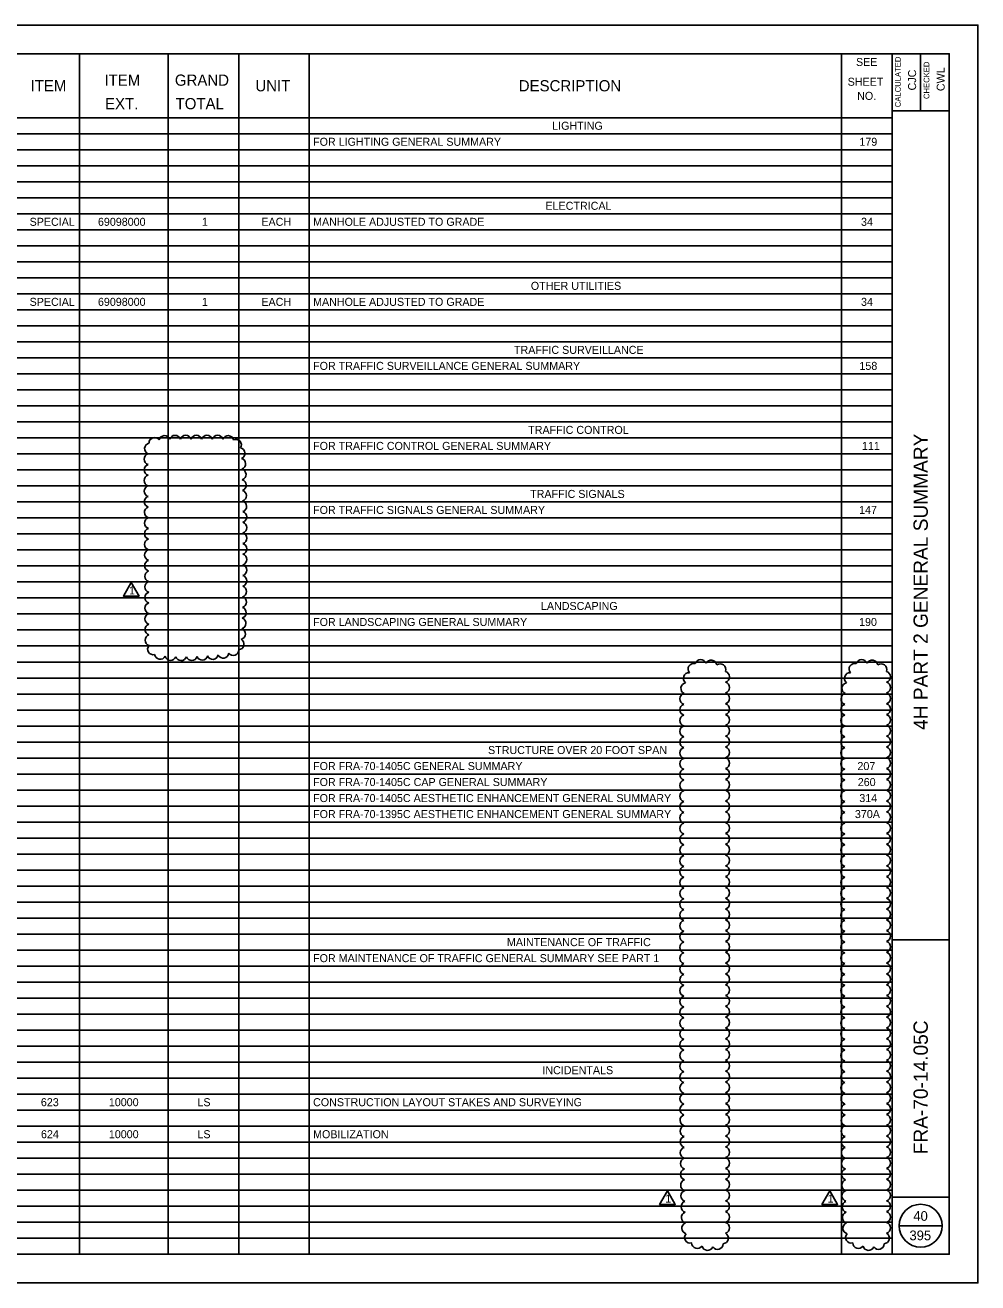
# Model space of a CAD drawing. Extents: x 0 to 34, y 0 to 22.
# Drawn here: x 17.34 to 34, y 0 to 22 of the extents above; entities that cross this region are included whole.
import ezdxf

# ---------------------------------------------------------------- set-up
doc = ezdxf.new("R2010")
doc.units = 0
for name, color, linetype in [('SH_Border', 7, 'Continuous'), ('SH_Cut_Line', 7, 'Continuous'), ('SH_Data', 7, 'Continuous'), ('SH_Text', 7, 'Continuous'), ('TX_P_1000', 7, 'Continuous')]:
    doc.layers.add(name, color=color, linetype=linetype)

msp = doc.modelspace()

# ---------------------------------------------------------------- linework, layer by layer
at = {"layer": 'SH_Border'}
for p, q in [((32.5, 0.5), (32.5, 21.5)), ((33, 21.5), (33, 20.5)), ((32.5, 20.5), (33.5, 20.5)), ((32.5, 6), (33.5, 6)), ((32.5, 1.5), (33.5, 1.5))]:
    msp.add_line(p, q, dxfattribs=at)
msp.add_lwpolyline([(2, 21.5), (33.5, 21.5), (33.5, 0.5), (2, 0.5)], close=True, dxfattribs=at)
at = {"layer": 'SH_Cut_Line'}
msp.add_lwpolyline([(0, 0), (34, 0), (34, 22), (0, 22)], close=True, dxfattribs=at)
at = {"layer": 'SH_Data'}
for p, q in [((17.252, 21.5), (32.504, 21.5)), ((18.289, 21.5), (18.289, 0.5)), ((19.838, 21.5), (19.838, 0.5)), ((21.073, 21.5), (21.073, 0.5)), ((22.308, 21.5), (22.308, 0.5)), ((31.614, 21.5), (31.614, 0.5)), ((32.504, 21.5), (32.504, 0.5)), ((2, 20.38), (32.504, 20.38)), ((2, 20.1), (32.504, 20.1)), ((2, 19.82), (32.504, 19.82)), ((2, 19.54), (32.504, 19.54)), ((2, 19.26), (32.504, 19.26)), ((2, 18.98), (32.504, 18.98)), ((2, 18.7), (32.504, 18.7)), ((2, 18.42), (32.504, 18.42)), ((2, 18.14), (32.504, 18.14)), ((2, 17.86), (32.504, 17.86)), ((2, 17.58), (32.504, 17.58)), ((2, 17.3), (32.504, 17.3)), ((2, 17.02), (32.504, 17.02)), ((2, 16.74), (32.504, 16.74)), ((2, 16.46), (32.504, 16.46)), ((2, 16.18), (32.504, 16.18)), ((2, 15.9), (32.504, 15.9)), ((2, 15.62), (32.504, 15.62)), ((2, 15.34), (32.504, 15.34)), ((2, 15.06), (32.504, 15.06)), ((2, 14.78), (32.504, 14.78)), ((2, 14.5), (32.504, 14.5)), ((2, 14.22), (32.504, 14.22)), ((2, 13.94), (32.504, 13.94)), ((2, 13.66), (32.504, 13.66)), ((2, 13.38), (32.504, 13.38)), ((2, 13.1), (32.504, 13.1)), ((2, 12.82), (32.504, 12.82)), ((2, 12.54), (32.504, 12.54)), ((2, 12.26), (32.504, 12.26)), ((2, 11.98), (32.504, 11.98)), ((2, 11.7), (32.504, 11.7)), ((2, 11.42), (32.504, 11.42)), ((2, 11.14), (32.504, 11.14)), ((2, 10.86), (32.504, 10.86)), ((2, 10.58), (32.504, 10.58)), ((2, 10.3), (32.504, 10.3)), ((2, 10.02), (32.504, 10.02)), ((2, 9.74), (32.504, 9.74)), ((2, 9.46), (32.504, 9.46)), ((2, 9.18), (32.504, 9.18)), ((2, 8.9), (32.504, 8.9)), ((2, 8.62), (32.504, 8.62)), ((2, 8.34), (32.504, 8.34)), ((2, 8.06), (32.504, 8.06)), ((2, 7.78), (32.504, 7.78)), ((2, 7.5), (32.504, 7.5)), ((2, 7.22), (32.504, 7.22)), ((2, 6.94), (32.504, 6.94)), ((2, 6.66), (32.504, 6.66)), ((2, 6.38), (32.504, 6.38)), ((2, 6.1), (32.504, 6.1)), ((2, 5.82), (32.504, 5.82)), ((2, 5.54), (32.504, 5.54)), ((2, 5.26), (32.504, 5.26)), ((2, 4.98), (32.504, 4.98)), ((2, 4.7), (32.504, 4.7)), ((2, 4.42), (32.504, 4.42)), ((2, 4.14), (32.504, 4.14)), ((2, 3.86), (32.504, 3.86)), ((2, 3.58), (32.504, 3.58)), ((2, 3.3), (32.504, 3.3)), ((2, 3.02), (32.504, 3.02)), ((2, 2.74), (32.504, 2.74)), ((2, 2.46), (32.504, 2.46)), ((2, 2.18), (32.504, 2.18)), ((2, 1.9), (32.504, 1.9)), ((2, 1.62), (32.504, 1.62)), ((2, 1.34), (32.504, 1.34)), ((2, 1.06), (32.504, 1.06)), ((32.625, 1), (33.375, 1)), ((2, 0.78), (32.504, 0.78)), ((2, 0.5), (32.504, 0.5))]:
    msp.add_line(p, q, dxfattribs=at)
msp.add_circle((33, 1), 0.375, dxfattribs=at)
at = {"layer": 'TX_P_1000'}
for points in [[(19.194, 12.249), (19.057, 12.013), (19.33, 12.013)], [(28.571, 1.608), (28.435, 1.372), (28.708, 1.372)], [(31.411, 1.608), (31.274, 1.372), (31.547, 1.372)]]:
    msp.add_lwpolyline(points, close=True, dxfattribs=at)
for centre, radius, start, end in [((19.602, 14.689), 0.0977, 36.7231, 181.7231), ((19.775, 14.722), 0.0976, 20.0252, 165.0252), ((19.96, 14.727), 0.0976, 18.0955, 163.0955), ((20.146, 14.728), 0.0976, 17.5007, 162.5007), ((20.332, 14.728), 0.0976, 17.5, 162.5), ((20.518, 14.728), 0.0976, 17.5, 162.5), ((20.704, 14.728), 0.0976, 17.4886, 162.4886), ((20.889, 14.722), 0.0976, 14.207, 159.207), ((21.023, 14.657), 0.0975, 328.8806, 113.8806), ((19.524, 14.59), 0.0975, 101.8161, 246.8161), ((21.085, 14.512), 0.0976, 292.072, 77.072), ((19.516, 14.408), 0.0976, 107.7774, 252.7774), ((19.517, 14.221), 0.0976, 107.7971, 252.7971), ((21.096, 14.327), 0.0976, 290.1112, 75.1112), ((19.518, 14.035), 0.0976, 107.805, 252.805), ((21.103, 14.141), 0.0976, 289.2389, 74.2389), ((19.519, 13.849), 0.0976, 107.8096, 252.8096), ((21.108, 13.955), 0.0976, 288.7142, 73.7142), ((21.111, 13.769), 0.0976, 288.3537, 73.3537), ((19.52, 13.663), 0.0976, 107.8127, 252.8127), ((21.114, 13.583), 0.0976, 288.0863, 73.0863), ((19.521, 13.477), 0.0976, 107.815, 252.815), ((21.115, 13.397), 0.0976, 287.8778, 72.8778), ((19.522, 13.29), 0.0976, 107.8168, 252.8168), ((21.116, 13.211), 0.0976, 287.7092, 72.7092), ((19.523, 13.104), 0.0976, 107.8182, 252.8182), ((19.524, 12.918), 0.0976, 107.8194, 252.8194), ((21.117, 13.025), 0.0976, 287.5693, 72.5693), ((19.525, 12.732), 0.0976, 107.8202, 252.8202), ((21.117, 12.839), 0.0976, 287.4584, 72.4584), ((19.526, 12.545), 0.0976, 107.8202, 252.8202), ((21.116, 12.653), 0.0976, 287.3535, 72.3535), ((21.116, 12.466), 0.0976, 287.2279, 72.2279), ((19.527, 12.359), 0.0976, 107.8202, 252.8202), ((21.115, 12.28), 0.0976, 287.0737, 72.0737), ((19.528, 12.173), 0.0976, 107.8202, 252.8202), ((21.113, 12.094), 0.0976, 286.8782, 71.8782), ((19.529, 11.987), 0.0976, 107.8202, 252.8202), ((19.53, 11.801), 0.0976, 107.8202, 252.8202), ((21.11, 11.908), 0.0976, 286.6187, 71.6187), ((19.531, 11.614), 0.0976, 107.8202, 252.8202), ((21.107, 11.722), 0.0976, 286.2502, 71.2502), ((19.532, 11.428), 0.0976, 107.8202, 252.8202), ((21.094, 11.351), 0.0976, 284.493, 69.493), ((21.102, 11.536), 0.0976, 285.6646, 70.6646), ((19.533, 11.242), 0.0976, 107.8202, 252.8202), ((21.068, 11.173), 0.0976, 273.9501, 58.9501), ((19.578, 11.085), 0.0976, 139.2641, 284.2641), ((20.803, 11.026), 0.0976, 206.7346, 351.7346), ((20.977, 11.072), 0.0977, 217.3339, 2.3339), ((19.699, 11.005), 0.0976, 188.32, 333.32), ((19.88, 10.986), 0.0976, 195.1082, 340.1082), ((20.065, 10.982), 0.0976, 197.1836, 342.1836), ((20.251, 10.983), 0.0976, 198.6029, 343.6029), ((20.436, 10.99), 0.0976, 200.3873, 345.3873), ((20.62, 11.003), 0.0976, 202.8824, 347.8824), ((29.031, 10.736), 0.099, 74.4093, 219.4093), ((29.153, 10.805), 0.0991, 19.2496, 164.2496), ((29.336, 10.794), 0.0991, 9.041, 154.041), ((29.491, 10.729), 0.099, 340.6755, 125.6755), ((31.847, 10.736), 0.099, 74.4093, 219.4093), ((31.969, 10.805), 0.0991, 19.2496, 164.2496), ((32.152, 10.794), 0.0991, 9.041, 154.041), ((32.308, 10.729), 0.099, 340.6755, 125.6755), ((28.95, 10.574), 0.0991, 87.314, 232.314), ((29.557, 10.601), 0.0992, 288.6913, 73.6913), ((31.766, 10.574), 0.0991, 87.314, 232.314), ((32.373, 10.601), 0.0992, 288.6913, 73.6913), ((28.906, 10.398), 0.0991, 99.6335, 244.6335), ((29.559, 10.413), 0.0991, 287.5, 72.5), ((31.722, 10.398), 0.0991, 99.6335, 244.6335), ((32.375, 10.413), 0.0991, 287.5, 72.5), ((28.889, 10.213), 0.0991, 105.2456, 250.2456), ((29.559, 10.224), 0.0991, 287.5, 72.5), ((29.559, 10.035), 0.0991, 287.5, 72.5), ((31.706, 10.213), 0.0991, 105.2456, 250.2456), ((32.375, 10.224), 0.0991, 287.5, 72.5), ((32.375, 10.035), 0.0991, 287.5, 72.5), ((28.886, 10.025), 0.0991, 107.4797, 252.4797), ((28.885, 9.836), 0.0991, 107.5, 252.5), ((29.559, 9.846), 0.0991, 287.5, 72.5), ((31.702, 10.025), 0.0991, 107.4797, 252.4797), ((31.702, 9.836), 0.0991, 107.5, 252.5), ((32.375, 9.846), 0.0991, 287.5, 72.5), ((28.885, 9.647), 0.0991, 107.5, 252.5), ((29.559, 9.657), 0.0991, 287.5, 72.5), ((31.702, 9.647), 0.0991, 107.5, 252.5), ((32.375, 9.657), 0.0991, 287.5, 72.5), ((28.885, 9.458), 0.0991, 107.5, 252.5), ((29.559, 9.468), 0.0991, 287.5, 72.5), ((31.702, 9.458), 0.0991, 107.5, 252.5), ((32.375, 9.468), 0.0991, 287.5, 72.5), ((28.885, 9.269), 0.0991, 107.5, 252.5), ((29.559, 9.279), 0.0991, 287.5, 72.5), ((31.702, 9.269), 0.0991, 107.5, 252.5), ((32.375, 9.279), 0.0991, 287.5, 72.5), ((28.885, 9.08), 0.0991, 107.5, 252.5), ((29.559, 9.09), 0.0991, 287.5, 72.5), ((31.702, 9.08), 0.0991, 107.5, 252.5), ((32.375, 9.09), 0.0991, 287.5, 72.5), ((28.885, 8.891), 0.0991, 107.5, 252.5), ((29.559, 8.901), 0.0991, 287.5, 72.5), ((29.559, 8.712), 0.0991, 287.5, 72.5), ((31.702, 8.891), 0.0991, 107.5, 252.5), ((32.375, 8.901), 0.0991, 287.5, 72.5), ((32.375, 8.712), 0.0991, 287.5, 72.5), ((28.885, 8.702), 0.0991, 107.5, 252.5), ((28.885, 8.513), 0.0991, 107.5, 252.5), ((29.559, 8.523), 0.0991, 287.5, 72.5), ((31.702, 8.702), 0.0991, 107.5, 252.5), ((31.702, 8.513), 0.0991, 107.5, 252.5), ((32.375, 8.523), 0.0991, 287.5, 72.5), ((28.885, 8.324), 0.0991, 107.5, 252.5), ((29.559, 8.334), 0.0991, 287.5, 72.5), ((31.702, 8.324), 0.0991, 107.5, 252.5), ((32.375, 8.334), 0.0991, 287.5, 72.5), ((28.885, 8.135), 0.0991, 107.5, 252.5), ((29.559, 8.145), 0.0991, 287.5, 72.5), ((31.702, 8.135), 0.0991, 107.5, 252.5), ((32.375, 8.145), 0.0991, 287.5, 72.5), ((28.885, 7.946), 0.0991, 107.5, 252.5), ((29.559, 7.956), 0.0991, 287.5, 72.5), ((31.702, 7.946), 0.0991, 107.5, 252.5), ((32.375, 7.956), 0.0991, 287.5, 72.5), ((28.885, 7.757), 0.0991, 107.5, 252.5), ((29.559, 7.767), 0.0991, 287.5, 72.5), ((31.702, 7.757), 0.0991, 107.5, 252.5), ((32.375, 7.767), 0.0991, 287.5, 72.5), ((28.885, 7.568), 0.0991, 107.5, 252.5), ((29.559, 7.578), 0.0991, 287.5, 72.5), ((29.559, 7.389), 0.0991, 287.5, 72.5), ((31.702, 7.568), 0.0991, 107.5, 252.5), ((32.375, 7.578), 0.0991, 287.5, 72.5), ((32.375, 7.389), 0.0991, 287.5, 72.5), ((28.885, 7.379), 0.0991, 107.5, 252.5), ((28.885, 7.19), 0.0991, 107.5, 252.5), ((29.559, 7.2), 0.0991, 287.5, 72.5), ((31.702, 7.379), 0.0991, 107.5, 252.5), ((31.702, 7.19), 0.0991, 107.5, 252.5), ((32.375, 7.2), 0.0991, 287.5, 72.5), ((28.885, 7.001), 0.0991, 107.5, 252.5), ((29.559, 7.011), 0.0991, 287.5, 72.5), ((31.702, 7.001), 0.0991, 107.5, 252.5), ((32.375, 7.011), 0.0991, 287.5, 72.5), ((28.885, 6.812), 0.0991, 107.5, 252.5), ((29.559, 6.822), 0.0991, 287.5, 72.5), ((31.702, 6.812), 0.0991, 107.5, 252.5), ((32.375, 6.822), 0.0991, 287.5, 72.5), ((28.885, 6.623), 0.0991, 107.5, 252.5), ((29.559, 6.633), 0.0991, 287.5, 72.5), ((31.702, 6.623), 0.0991, 107.5, 252.5), ((32.375, 6.633), 0.0991, 287.5, 72.5), ((28.885, 6.434), 0.0991, 107.5, 252.5), ((29.559, 6.444), 0.0991, 287.5, 72.5), ((31.702, 6.434), 0.0991, 107.5, 252.5), ((32.375, 6.444), 0.0991, 287.5, 72.5), ((28.885, 6.245), 0.0991, 107.5, 252.5), ((29.559, 6.255), 0.0991, 287.5, 72.5), ((29.559, 6.066), 0.0991, 287.5, 72.5), ((31.702, 6.245), 0.0991, 107.5, 252.5), ((32.375, 6.255), 0.0991, 287.5, 72.5), ((32.375, 6.066), 0.0991, 287.5, 72.5), ((28.885, 6.056), 0.0991, 107.5, 252.5), ((28.885, 5.867), 0.0991, 107.5, 252.5), ((29.559, 5.877), 0.0991, 287.5, 72.5), ((31.702, 6.056), 0.0991, 107.5, 252.5), ((31.702, 5.867), 0.0991, 107.5, 252.5), ((32.375, 5.877), 0.0991, 287.5, 72.5), ((28.885, 5.678), 0.0991, 107.5, 252.5), ((29.559, 5.688), 0.0991, 287.5, 72.5), ((31.702, 5.678), 0.0991, 107.5, 252.5), ((32.375, 5.688), 0.0991, 287.5, 72.5), ((28.885, 5.489), 0.0991, 107.5, 252.5), ((29.559, 5.499), 0.0991, 287.5, 72.5), ((31.702, 5.489), 0.0991, 107.5, 252.5), ((32.375, 5.499), 0.0991, 287.5, 72.5), ((28.885, 5.3), 0.0991, 107.5, 252.5), ((29.559, 5.31), 0.0991, 287.5, 72.5), ((31.702, 5.3), 0.0991, 107.5, 252.5), ((32.375, 5.31), 0.0991, 287.5, 72.5), ((28.886, 5.111), 0.0991, 107.5091, 252.5091), ((29.559, 5.121), 0.0991, 287.5, 72.5), ((31.702, 5.111), 0.0991, 107.5091, 252.5091), ((32.375, 5.121), 0.0991, 287.5, 72.5), ((28.886, 4.922), 0.0991, 107.5258, 252.5258), ((29.559, 4.932), 0.0991, 287.5, 72.5), ((31.702, 4.922), 0.0991, 107.5258, 252.5258), ((32.375, 4.932), 0.0991, 287.5, 72.5), ((28.886, 4.733), 0.0991, 107.5437, 252.5437), ((28.886, 4.544), 0.0991, 107.5629, 252.5629), ((29.559, 4.743), 0.0991, 287.5, 72.5), ((29.559, 4.554), 0.0991, 287.5, 72.5), ((31.702, 4.733), 0.0991, 107.5437, 252.5437), ((31.702, 4.544), 0.0991, 107.5629, 252.5629), ((32.375, 4.743), 0.0991, 287.5, 72.5), ((32.375, 4.554), 0.0991, 287.5, 72.5), ((28.886, 4.355), 0.0991, 107.5836, 252.5836), ((29.559, 4.365), 0.0991, 287.5, 72.5), ((31.703, 4.355), 0.0991, 107.5836, 252.5836), ((32.375, 4.365), 0.0991, 287.5, 72.5), ((28.886, 4.166), 0.0991, 107.606, 252.606), ((29.559, 4.176), 0.0991, 287.5, 72.5), ((31.703, 4.166), 0.0991, 107.606, 252.606), ((32.375, 4.176), 0.0991, 287.5, 72.5), ((28.887, 3.977), 0.0991, 107.6303, 252.6303), ((29.559, 3.987), 0.0991, 287.5, 72.5), ((31.703, 3.977), 0.0991, 107.6303, 252.6303), ((32.375, 3.987), 0.0991, 287.5, 72.5), ((28.887, 3.788), 0.0991, 107.6568, 252.6568), ((29.559, 3.797), 0.0991, 287.5, 72.5), ((31.704, 3.788), 0.0991, 107.6568, 252.6568), ((32.375, 3.797), 0.0991, 287.5, 72.5), ((28.888, 3.599), 0.0991, 107.6859, 252.6859), ((29.559, 3.608), 0.0991, 287.5, 72.5), ((31.704, 3.599), 0.0991, 107.6859, 252.6859), ((32.375, 3.608), 0.0991, 287.5, 72.5), ((28.889, 3.41), 0.0991, 107.718, 252.718), ((28.889, 3.221), 0.0991, 107.7537, 252.7537), ((29.559, 3.419), 0.0991, 287.5, 72.5), ((29.559, 3.23), 0.0991, 287.5, 72.5), ((31.705, 3.41), 0.0991, 107.718, 252.718), ((31.706, 3.221), 0.0991, 107.7537, 252.7537), ((32.375, 3.419), 0.0991, 287.5, 72.5), ((32.375, 3.23), 0.0991, 287.5, 72.5), ((28.89, 3.032), 0.0991, 107.7938, 252.7938), ((29.559, 3.041), 0.0991, 287.5, 72.5), ((31.707, 3.032), 0.0991, 107.7938, 252.7938), ((32.375, 3.041), 0.0991, 287.5, 72.5), ((28.891, 2.843), 0.0991, 107.8391, 252.8391), ((29.559, 2.852), 0.0991, 287.5, 72.5), ((31.708, 2.843), 0.0991, 107.8391, 252.8391), ((32.375, 2.852), 0.0991, 287.5, 72.5), ((28.892, 2.654), 0.0991, 107.8909, 252.8909), ((29.559, 2.663), 0.0991, 287.5, 72.5), ((31.709, 2.654), 0.0991, 107.8909, 252.8909), ((32.375, 2.663), 0.0991, 287.5, 72.5), ((28.894, 2.465), 0.0991, 107.951, 252.951), ((29.559, 2.474), 0.0991, 287.5, 72.5), ((31.71, 2.465), 0.0991, 107.951, 252.951), ((32.375, 2.474), 0.0991, 287.5, 72.5), ((28.895, 2.276), 0.0991, 108.0219, 253.0219), ((29.559, 2.285), 0.0991, 287.5, 72.5), ((31.712, 2.276), 0.0991, 108.0219, 253.0219), ((32.375, 2.285), 0.0991, 287.5, 72.5), ((28.897, 2.087), 0.0991, 108.1071, 253.1071), ((28.899, 1.898), 0.0991, 108.2123, 253.2123), ((29.559, 2.096), 0.0991, 287.5, 72.5), ((29.559, 1.907), 0.0991, 287.5, 72.5), ((31.714, 2.087), 0.0991, 108.1071, 253.1071), ((31.716, 1.898), 0.0991, 108.2123, 253.2123), ((32.375, 2.096), 0.0991, 287.5, 72.5), ((32.375, 1.907), 0.0991, 287.5, 72.5), ((28.902, 1.709), 0.0991, 108.3469, 253.3469), ((29.559, 1.718), 0.0991, 287.5, 72.5), ((31.719, 1.709), 0.0991, 108.3469, 253.3469), ((32.375, 1.718), 0.0991, 287.5, 72.5), ((28.905, 1.521), 0.0991, 108.5276, 253.5276), ((29.559, 1.529), 0.0991, 287.5, 72.5), ((31.722, 1.521), 0.0991, 108.5276, 253.5276), ((32.375, 1.529), 0.0991, 287.5, 72.5), ((28.909, 1.332), 0.0991, 108.7891, 253.7891), ((29.559, 1.34), 0.0991, 287.5, 72.5), ((31.725, 1.332), 0.0991, 108.7891, 253.7891), ((32.375, 1.34), 0.0991, 287.5, 72.5), ((28.914, 1.143), 0.0991, 109.2189, 254.2189), ((29.559, 1.151), 0.0991, 287.5, 72.5), ((31.73, 1.143), 0.0991, 109.2189, 254.2189), ((32.375, 1.151), 0.0991, 287.5, 72.5), ((28.921, 0.955), 0.0991, 110.1571, 255.1571), ((29.559, 0.962), 0.0991, 287.5, 72.5), ((31.738, 0.955), 0.0991, 110.1571, 255.1571), ((32.375, 0.962), 0.0991, 287.5, 72.5), ((28.971, 0.794), 0.0991, 139.2663, 284.2663), ((29.094, 0.7), 0.0991, 180.783, 325.783), ((29.446, 0.685), 0.0991, 214.5703, 359.5703), ((29.538, 0.783), 0.0991, 274.2898, 59.2898), ((31.787, 0.794), 0.0991, 139.2663, 284.2663), ((31.911, 0.7), 0.0991, 180.783, 325.783), ((32.263, 0.685), 0.0991, 214.5703, 359.5703), ((32.354, 0.783), 0.0991, 274.2898, 59.2898), ((29.273, 0.666), 0.0991, 192.8167, 337.8167), ((32.089, 0.666), 0.0991, 192.8167, 337.8167)]:
    msp.add_arc(centre, radius, start, end, dxfattribs=at)

# ---------------------------------------------------------------- texts
at = {"layer": 'SH_Data'}
for s, height, p in [('CALCULATED', 0.1, (32.652, 20.565)), ('CHECKED', 0.1, (33.152, 20.708)), ('CJC', 0.14, (32.92, 20.858)), ('CWL', 0.14, (33.42, 20.846)), ('4H PART 2 GENERAL SUMMARY', 0.25, (33.125, 9.672)), ('FRA-70-14.05C', 0.25, (33.125, 2.249))]:
    msp.add_text(s, height=height, rotation=90, dxfattribs=at).set_placement(p)
at = {"layer": 'SH_Text'}
for s, height, p in [('SEE', 0.14, (31.869, 21.286)), ('ITEM', 0.196, (18.725, 20.94)), ('GRAND', 0.196, (19.957, 20.94)), ('ITEM', 0.196, (17.432, 20.842)), ('UNIT', 0.196, (21.365, 20.842)), ('DESCRIPTION', 0.196, (25.971, 20.842)), ('SHEET', 0.14, (31.723, 20.94)), ('EXT.', 0.196, (18.735, 20.529)), ('TOTAL', 0.196, (19.969, 20.529)), ('NO.', 0.14, (31.889, 20.693)), ('LIGHTING', 0.14, (26.556, 20.17)), ('FOR LIGHTING GENERAL SUMMARY', 0.14, (22.374, 19.89)), ('179', 0.14, (31.928, 19.89)), ('ELECTRICAL', 0.14, (26.438, 18.77)), ('SPECIAL', 0.14, (17.416, 18.49)), ('69098000', 0.14, (18.611, 18.49)), ('1', 0.14, (20.429, 18.49)), ('EACH', 0.14, (21.469, 18.49)), ('MANHOLE ADJUSTED TO GRADE', 0.14, (22.374, 18.49)), ('34', 0.14, (31.957, 18.49)), ('OTHER UTILITIES', 0.14, (26.182, 17.37)), ('SPECIAL', 0.14, (17.416, 17.09)), ('69098000', 0.14, (18.611, 17.09)), ('1', 0.14, (20.429, 17.09)), ('EACH', 0.14, (21.469, 17.09)), ('MANHOLE ADJUSTED TO GRADE', 0.14, (22.374, 17.09)), ('34', 0.14, (31.957, 17.09)), ('TRAFFIC SURVEILLANCE', 0.14, (25.887, 16.25)), ('FOR TRAFFIC SURVEILLANCE GENERAL SUMMARY', 0.14, (22.374, 15.97)), ('158', 0.14, (31.929, 15.97)), ('TRAFFIC CONTROL', 0.14, (26.136, 14.85)), ('FOR TRAFFIC CONTROL GENERAL SUMMARY', 0.14, (22.374, 14.57)), ('111', 0.14, (31.973, 14.57)), ('TRAFFIC SIGNALS', 0.14, (26.17, 13.73)), ('FOR TRAFFIC SIGNALS GENERAL SUMMARY', 0.14, (22.374, 13.45)), ('147', 0.14, (31.923, 13.45)), ('LANDSCAPING', 0.14, (26.359, 11.77)), ('FOR LANDSCAPING GENERAL SUMMARY', 0.14, (22.374, 11.49)), ('190', 0.14, (31.923, 11.49)), ('STRUCTURE OVER 20 FOOT SPAN', 0.14, (25.434, 9.25)), ('FOR FRA-70-1405C GENERAL SUMMARY', 0.14, (22.374, 8.97)), ('207', 0.14, (31.894, 8.97)), ('FOR FRA-70-1405C CAP GENERAL SUMMARY', 0.14, (22.374, 8.69)), ('260', 0.14, (31.9, 8.69)), ('FOR FRA-70-1405C AESTHETIC ENHANCEMENT GENERAL SUMMARY', 0.14, (22.374, 8.41)), ('314', 0.14, (31.927, 8.41)), ('FOR FRA-70-1395C AESTHETIC ENHANCEMENT GENERAL SUMMARY', 0.14, (22.374, 8.13)), ('370A', 0.14, (31.85, 8.13)), ('MAINTENANCE OF TRAFFIC', 0.14, (25.764, 5.89)), ('FOR MAINTENANCE OF TRAFFIC GENERAL SUMMARY SEE PART 1', 0.14, (22.374, 5.61)), ('INCIDENTALS', 0.14, (26.384, 3.65)), ('623', 0.14, (17.613, 3.09)), ('10000', 0.14, (18.802, 3.09)), ('LS', 0.14, (20.351, 3.09)), ('CONSTRUCTION LAYOUT STAKES AND SURVEYING', 0.14, (22.374, 3.09)), ('624', 0.14, (17.615, 2.53)), ('10000', 0.14, (18.802, 2.53)), ('LS', 0.14, (20.351, 2.53)), ('MOBILIZATION', 0.14, (22.374, 2.53)), ('40', 0.17, (32.872, 1.085)), ('395', 0.17, (32.804, 0.745))]:
    msp.add_text(s, height=height, dxfattribs=at).set_placement(p)
at = {"layer": 'TX_P_1000'}
for p in [(19.155, 12.043), (28.532, 1.403), (31.372, 1.403)]:
    msp.add_text('1', height=0.14, rotation=360, dxfattribs=at).set_placement(p)

doc.saveas('drawing.dxf')
